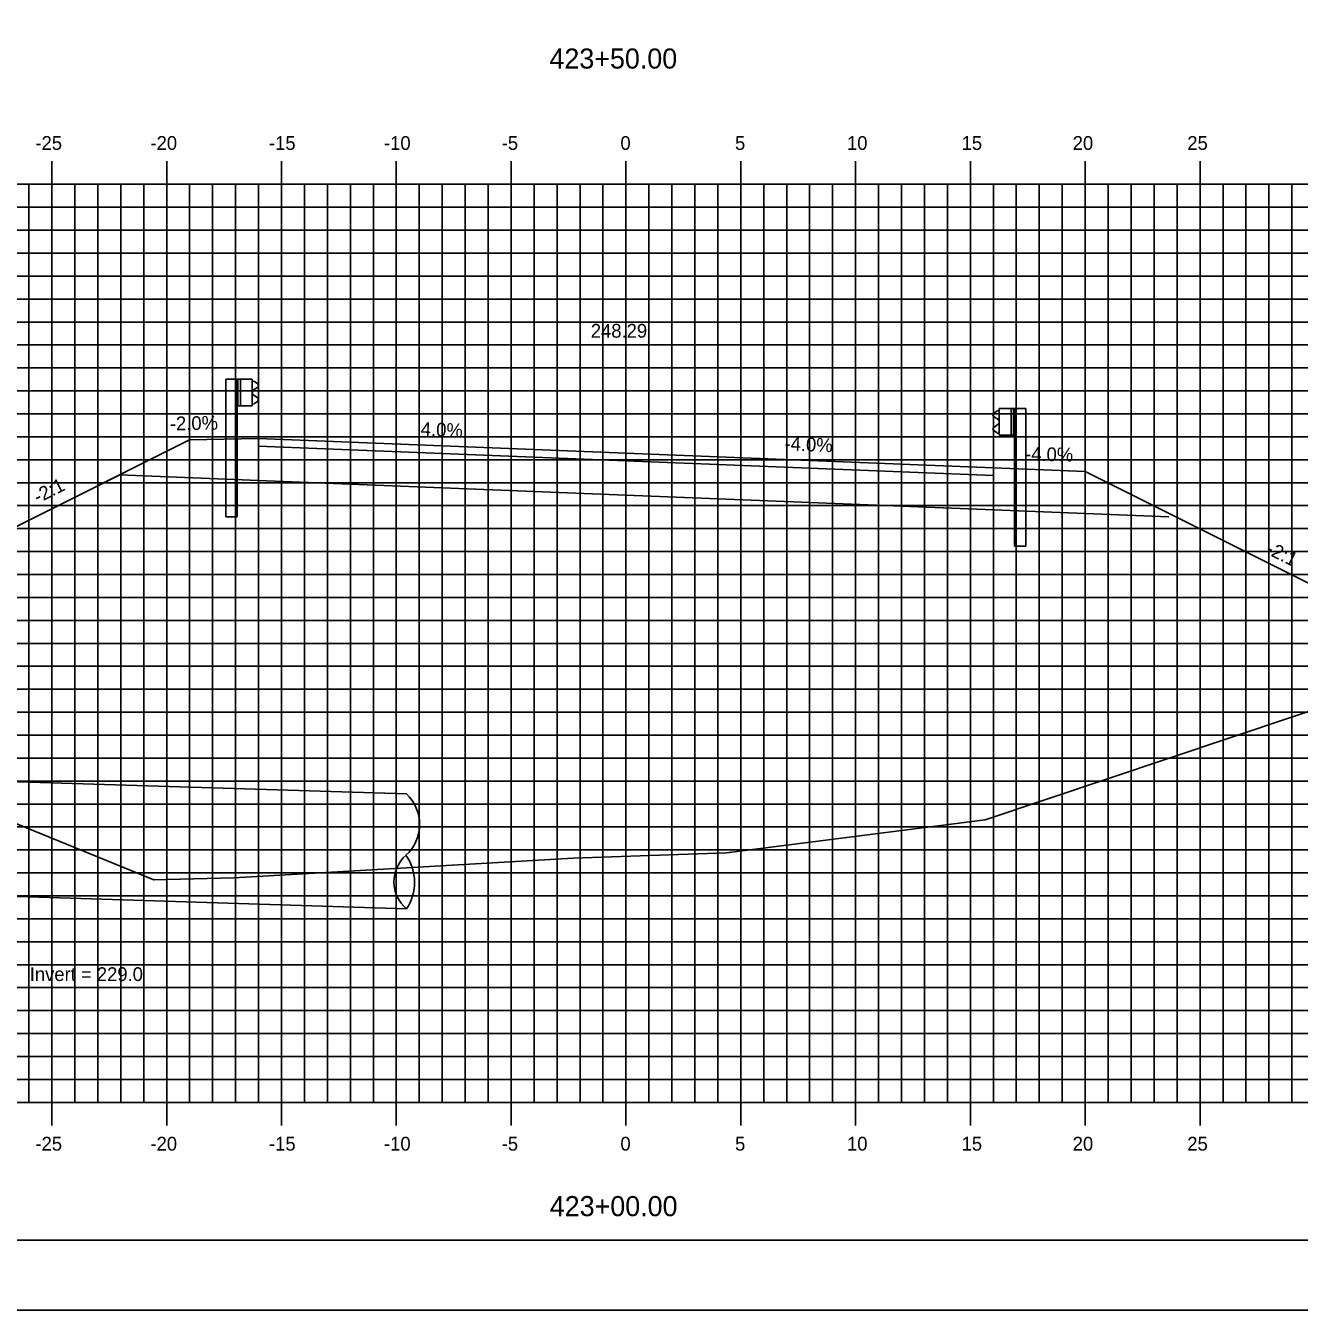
# Model space of a CAD drawing. Extents: x 1160718 to 1173142, y 616002 to 617630.
# Drawn here: x 1170158 to 1170213.5, y 616613.9 to 616669.8 of the extents above; entities that cross this region are included whole.
import ezdxf

# ---------------------------------------------------------------- set-up
doc = ezdxf.new("R2010")
doc.units = 0
for name, color, linetype in [('ANNOTATION', 7, 'Continuous'), ('BORDER', 7, 'Continuous'), ('D_Drainage_Text', 7, 'Continuous'), ('D_Guardrail_Beam_Lt', 7, 'Continuous'), ('D_Guardrail_Beam_Rt', 7, 'Continuous'), ('D_Roadway_Centerline', 7, 'Continuous'), ('D_Roadway_Centerline_Text', 7, 'Continuous'), ('D_Roadway_Edge_Shoulder', 7, 'Continuous'), ('D_Roadway_Edge_TW', 7, 'Continuous'), ('D_Roadway_Pavement', 7, 'Continuous'), ('D_Roadway_SlopeLines', 7, 'Continuous'), ('D_Roadway_SubGrade', 7, 'Continuous'), ('H_V ANNOTATION', 7, 'Continuous'), ('MAJOR', 7, 'Continuous'), ('MINOR', 7, 'Continuous'), ('PLOT BOUNDARY', 7, 'Continuous'), ('S_Roadway_Centerline', 7, 'Continuous'), ('SHADING', 7, 'Continuous')]:
    doc.layers.add(name, color=color, linetype=linetype)

msp = doc.modelspace()

# ---------------------------------------------------------------- linework, layer by layer
at = {"layer": 'ANNOTATION'}
msp.add_line((1170200.151, 616650.575), (1170204.151, 616650.415), dxfattribs=at)
at = {"layer": 'BORDER'}
msp.add_line((1170109.151, 616616.928), (1170269.151, 616616.928), dxfattribs=at)
at = {"layer": 'D_Drainage_Text'}
for p, q in [((1170174.597, 616636.365), (1170155.309, 616636.976)), ((1170174.597, 616631.363), (1170155.309, 616631.974))]:
    msp.add_line(p, q, dxfattribs=at)
for centre, radius, start, end in [((1170173.344, 616635.042), 1.822, 312.4159, 46.5629), ((1170175.585, 616632.54), 1.537, 131.1675, 229.9998), ((1170172.881, 616632.512), 2.065, 326.1716, 34.9956)]:
    msp.add_arc(centre, radius, start, end, dxfattribs=at)
at = {"layer": 'D_Guardrail_Beam_Lt'}
for p, q in [((1170166.723, 616654.439), (1170166.723, 616648.439)), ((1170167.194, 616654.439), (1170166.723, 616654.439)), ((1170167.881, 616654.439), (1170167.194, 616654.439)), ((1170167.194, 616654.439), (1170167.194, 616653.272)), ((1170167.256, 616654.439), (1170167.256, 616653.272)), ((1170167.36, 616654.439), (1170167.36, 616653.272)), ((1170167.881, 616653.272), (1170167.881, 616654.439)), ((1170167.881, 616654.355), (1170167.955, 616654.341)), ((1170168.114, 616654.091), (1170167.919, 616653.955)), ((1170167.971, 616654.334), (1170168.114, 616654.234)), ((1170167.885, 616653.89), (1170167.885, 616653.82)), ((1170167.919, 616653.756), (1170168.114, 616653.62)), ((1170168.114, 616653.476), (1170167.971, 616653.376)), ((1170167.194, 616653.272), (1170167.881, 616653.272)), ((1170167.214, 616648.439), (1170167.214, 616653.272)), ((1170167.955, 616653.37), (1170167.881, 616653.355)), ((1170167.214, 616648.439), (1170166.723, 616648.439))]:
    msp.add_line(p, q, dxfattribs=at)
for centre, major_axis, start_param, end_param in [((1170167.964, 616653.89), (-0.0789, 0), 5.323254, 6.283185), ((1170167.947, 616654.3), (0.0417, 0), 0.959931, 1.376053), ((1170168.064, 616654.162), (0.0877, 0), 5.323254, 7.243116), ((1170167.964, 616653.82), (-0.0789, 0), 6.283185, 7.243116), ((1170167.947, 616653.41), (0.0417, 0), 4.907132, 5.323254), ((1170168.064, 616653.548), (0.0877, 0), 5.323254, 7.243116)]:
    msp.add_ellipse(centre, major_axis=major_axis, ratio=0.995501, start_param=start_param, end_param=end_param, dxfattribs=at)
at = {"layer": 'D_Guardrail_Beam_Rt'}
for p, q in [((1170200.315, 616653.055), (1170200.172, 616652.955)), ((1170200.405, 616653.076), (1170200.331, 616653.061)), ((1170200.405, 616653.159), (1170201.092, 616653.159)), ((1170200.405, 616651.993), (1170200.405, 616653.159)), ((1170200.926, 616653.159), (1170200.926, 616651.993)), ((1170201.03, 616653.159), (1170201.03, 616651.993)), ((1170201.092, 616653.159), (1170201.563, 616653.159)), ((1170201.092, 616653.159), (1170201.092, 616651.993)), ((1170201.563, 616653.159), (1170201.563, 616647.159)), ((1170200.172, 616652.812), (1170200.367, 616652.675)), ((1170200.367, 616652.476), (1170200.172, 616652.34)), ((1170200.401, 616652.611), (1170200.401, 616652.541)), ((1170200.172, 616652.197), (1170200.315, 616652.097)), ((1170200.331, 616652.09), (1170200.405, 616652.076)), ((1170201.092, 616651.993), (1170200.405, 616651.993)), ((1170201.072, 616647.159), (1170201.072, 616651.993)), ((1170201.072, 616647.159), (1170201.563, 616647.159))]:
    msp.add_line(p, q, dxfattribs=at)
for centre, major_axis, start_param, end_param in [((1170200.222, 616652.883), (-0.0877, 0), 5.323254, 7.243116), ((1170200.339, 616653.021), (-0.0417, 0), 4.907132, 5.323254), ((1170200.222, 616652.269), (-0.0877, 0), 5.323254, 7.243116), ((1170200.322, 616652.611), (0.0789, 0), 0, 0.959931), ((1170200.322, 616652.541), (0.0789, 0), 5.323254, 6.283185), ((1170200.339, 616652.131), (-0.0417, 0), 0.959931, 1.376053)]:
    msp.add_ellipse(centre, major_axis=major_axis, ratio=0.995501, start_param=start_param, end_param=end_param, dxfattribs=at)
at = {"layer": 'D_Roadway_Edge_Shoulder'}
for points in [[(1170168.151, 616651.855), (1170168.151, 616651.522)], [(1170200.151, 616650.575), (1170200.151, 616650.242)]]:
    msp.add_lwpolyline(points, dxfattribs=at)
at = {"layer": 'D_Roadway_Edge_TW'}
msp.add_lwpolyline([(1170168.151, 616651.522), (1170168.151, 616651.855), (1170184.151, 616651.215), (1170200.151, 616650.575), (1170200.151, 616650.242), (1170184.151, 616650.882)], close=True, dxfattribs=at)
at = {"layer": 'D_Roadway_Pavement'}
msp.add_lwpolyline([(1170168.151, 616651.522), (1170168.151, 616651.522), (1170184.151, 616650.882), (1170200.151, 616650.242), (1170200.151, 616650.242), (1170184.151, 616650.882)], close=True, dxfattribs=at)
for points in [[(1170168.151, 616651.522), (1170168.151, 616651.522)], [(1170168.151, 616651.522), (1170168.151, 616651.522)], [(1170200.151, 616650.242), (1170200.151, 616650.242)], [(1170200.151, 616650.242), (1170200.151, 616650.242)]]:
    msp.add_lwpolyline(points, dxfattribs=at)
at = {"layer": 'D_Roadway_SlopeLines'}
msp.add_lwpolyline([(1170165.151, 616651.795), (1170154.068, 616646.254)], dxfattribs=at)
at = {"layer": 'D_Roadway_SubGrade'}
for p, q in [((1170165.151, 616651.795), (1170161.163, 616649.801)), ((1170168.151, 616651.855), (1170165.151, 616651.795)), ((1170168.151, 616650.022), (1170168.151, 616651.855)), ((1170168.151, 616650.022), (1170168.151, 616651.522)), ((1170168.151, 616651.522), (1170184.151, 616650.882)), ((1170184.151, 616650.882), (1170200.151, 616650.242)), ((1170200.151, 616648.742), (1170200.151, 616650.575)), ((1170200.151, 616650.242), (1170200.151, 616648.742)), ((1170204.151, 616650.415), (1170220.578, 616642.202))]:
    msp.add_line(p, q, dxfattribs=at)
at = {"layer": 'MAJOR'}
for p, q in [((1170159.151, 616663.93), (1170159.151, 616662.928)), ((1170164.151, 616663.93), (1170164.151, 616662.928)), ((1170169.151, 616663.93), (1170169.151, 616662.928)), ((1170174.151, 616663.93), (1170174.151, 616662.928)), ((1170179.151, 616663.93), (1170179.151, 616662.928)), ((1170184.151, 616663.93), (1170184.151, 616662.928)), ((1170189.151, 616663.93), (1170189.151, 616662.928)), ((1170194.151, 616663.93), (1170194.151, 616662.928)), ((1170199.151, 616663.93), (1170199.151, 616662.928)), ((1170204.151, 616663.93), (1170204.151, 616662.928)), ((1170209.151, 616663.93), (1170209.151, 616662.928)), ((1170114.151, 616662.928), (1170254.151, 616662.928)), ((1170114.151, 616662.928), (1170254.151, 616662.928)), ((1170159.151, 616622.928), (1170159.151, 616662.928)), ((1170164.151, 616622.928), (1170164.151, 616662.928)), ((1170169.151, 616622.928), (1170169.151, 616662.928)), ((1170174.151, 616622.928), (1170174.151, 616662.928)), ((1170179.151, 616622.928), (1170179.151, 616662.928)), ((1170184.151, 616622.928), (1170184.151, 616662.928)), ((1170189.151, 616622.928), (1170189.151, 616662.928)), ((1170194.151, 616622.928), (1170194.151, 616662.928)), ((1170199.151, 616622.928), (1170199.151, 616662.928)), ((1170204.151, 616622.928), (1170204.151, 616662.928)), ((1170209.151, 616622.928), (1170209.151, 616662.928)), ((1170114.151, 616657.928), (1170254.151, 616657.928)), ((1170114.151, 616652.928), (1170254.151, 616652.928)), ((1170114.151, 616647.928), (1170254.151, 616647.928)), ((1170114.151, 616642.928), (1170254.151, 616642.928)), ((1170114.151, 616637.928), (1170254.151, 616637.928)), ((1170114.151, 616632.928), (1170254.151, 616632.928)), ((1170114.151, 616627.928), (1170254.151, 616627.928)), ((1170114.151, 616622.928), (1170254.151, 616622.928)), ((1170114.151, 616622.928), (1170254.151, 616622.928)), ((1170159.151, 616621.926), (1170159.151, 616622.928)), ((1170164.151, 616621.926), (1170164.151, 616622.928)), ((1170169.151, 616621.926), (1170169.151, 616622.928)), ((1170174.151, 616621.926), (1170174.151, 616622.928)), ((1170179.151, 616621.926), (1170179.151, 616622.928)), ((1170184.151, 616621.926), (1170184.151, 616622.928)), ((1170189.151, 616621.926), (1170189.151, 616622.928)), ((1170194.151, 616621.926), (1170194.151, 616622.928)), ((1170199.151, 616621.926), (1170199.151, 616622.928)), ((1170204.151, 616621.926), (1170204.151, 616622.928)), ((1170209.151, 616621.926), (1170209.151, 616622.928))]:
    msp.add_line(p, q, dxfattribs=at)
at = {"layer": 'MINOR'}
for p, q in [((1170158.151, 616622.928), (1170158.151, 616662.928)), ((1170160.151, 616622.928), (1170160.151, 616662.928)), ((1170161.151, 616622.928), (1170161.151, 616662.928)), ((1170162.151, 616622.928), (1170162.151, 616662.928)), ((1170163.151, 616622.928), (1170163.151, 616662.928)), ((1170165.151, 616622.928), (1170165.151, 616662.928)), ((1170166.151, 616622.928), (1170166.151, 616662.928)), ((1170167.151, 616622.928), (1170167.151, 616662.928)), ((1170168.151, 616622.928), (1170168.151, 616662.928)), ((1170170.151, 616622.928), (1170170.151, 616662.928)), ((1170171.151, 616622.928), (1170171.151, 616662.928)), ((1170172.151, 616622.928), (1170172.151, 616662.928)), ((1170173.151, 616622.928), (1170173.151, 616662.928)), ((1170175.151, 616622.928), (1170175.151, 616662.928)), ((1170176.151, 616622.928), (1170176.151, 616662.928)), ((1170177.151, 616622.928), (1170177.151, 616662.928)), ((1170178.151, 616622.928), (1170178.151, 616662.928)), ((1170180.151, 616622.928), (1170180.151, 616662.928)), ((1170181.151, 616622.928), (1170181.151, 616662.928)), ((1170182.151, 616622.928), (1170182.151, 616662.928)), ((1170183.151, 616622.928), (1170183.151, 616662.928)), ((1170185.151, 616622.928), (1170185.151, 616662.928)), ((1170186.151, 616622.928), (1170186.151, 616662.928)), ((1170187.151, 616622.928), (1170187.151, 616662.928)), ((1170188.151, 616622.928), (1170188.151, 616662.928)), ((1170190.151, 616622.928), (1170190.151, 616662.928)), ((1170191.151, 616622.928), (1170191.151, 616662.928)), ((1170192.151, 616622.928), (1170192.151, 616662.928)), ((1170193.151, 616622.928), (1170193.151, 616662.928)), ((1170195.151, 616622.928), (1170195.151, 616662.928)), ((1170196.151, 616622.928), (1170196.151, 616662.928)), ((1170197.151, 616622.928), (1170197.151, 616662.928)), ((1170198.151, 616622.928), (1170198.151, 616662.928)), ((1170200.151, 616622.928), (1170200.151, 616662.928)), ((1170201.151, 616622.928), (1170201.151, 616662.928)), ((1170202.151, 616622.928), (1170202.151, 616662.928)), ((1170203.151, 616622.928), (1170203.151, 616662.928)), ((1170205.151, 616622.928), (1170205.151, 616662.928)), ((1170206.151, 616622.928), (1170206.151, 616662.928)), ((1170207.151, 616622.928), (1170207.151, 616662.928)), ((1170208.151, 616622.928), (1170208.151, 616662.928)), ((1170210.151, 616622.928), (1170210.151, 616662.928)), ((1170211.151, 616622.928), (1170211.151, 616662.928)), ((1170212.151, 616622.928), (1170212.151, 616662.928)), ((1170213.151, 616622.928), (1170213.151, 616662.928)), ((1170114.151, 616661.928), (1170254.151, 616661.928)), ((1170114.151, 616660.928), (1170254.151, 616660.928)), ((1170114.151, 616659.928), (1170254.151, 616659.928)), ((1170114.151, 616658.928), (1170254.151, 616658.928)), ((1170114.151, 616656.928), (1170254.151, 616656.928)), ((1170114.151, 616655.928), (1170254.151, 616655.928)), ((1170114.151, 616654.928), (1170254.151, 616654.928)), ((1170114.151, 616653.928), (1170254.151, 616653.928)), ((1170114.151, 616651.928), (1170254.151, 616651.928)), ((1170114.151, 616650.928), (1170254.151, 616650.928)), ((1170114.151, 616649.928), (1170254.151, 616649.928)), ((1170114.151, 616648.928), (1170254.151, 616648.928)), ((1170114.151, 616646.928), (1170254.151, 616646.928)), ((1170114.151, 616645.928), (1170254.151, 616645.928)), ((1170114.151, 616644.928), (1170254.151, 616644.928)), ((1170114.151, 616643.928), (1170254.151, 616643.928)), ((1170114.151, 616641.928), (1170254.151, 616641.928)), ((1170114.151, 616640.928), (1170254.151, 616640.928)), ((1170114.151, 616639.928), (1170254.151, 616639.928)), ((1170114.151, 616638.928), (1170254.151, 616638.928)), ((1170114.151, 616636.928), (1170254.151, 616636.928)), ((1170114.151, 616635.928), (1170254.151, 616635.928)), ((1170114.151, 616634.928), (1170254.151, 616634.928)), ((1170114.151, 616633.928), (1170254.151, 616633.928)), ((1170114.151, 616631.928), (1170254.151, 616631.928)), ((1170114.151, 616630.928), (1170254.151, 616630.928)), ((1170114.151, 616629.928), (1170254.151, 616629.928)), ((1170114.151, 616628.928), (1170254.151, 616628.928)), ((1170114.151, 616626.928), (1170254.151, 616626.928)), ((1170114.151, 616625.928), (1170254.151, 616625.928)), ((1170114.151, 616624.928), (1170254.151, 616624.928)), ((1170114.151, 616623.928), (1170254.151, 616623.928))]:
    msp.add_line(p, q, dxfattribs=at)
at = {"layer": 'PLOT BOUNDARY'}
msp.add_lwpolyline([(1170101.057, 616613.869), (1170271.057, 616613.869), (1170271.057, 616723.869), (1170101.057, 616723.869)], close=True, dxfattribs=at)
at = {"layer": 'S_Roadway_Centerline'}
msp.add_lwpolyline([(1170114.151, 616654.034), (1170119.443, 616651.554), (1170130.924, 616646.199), (1170135.528, 616644.078), (1170163.591, 616632.625), (1170167.073, 616632.713), (1170181.848, 616633.572), (1170188.523, 616633.797), (1170199.794, 616635.233), (1170245.321, 616650.498), (1170254.151, 616652.947)], dxfattribs=at)
at = {"layer": 'SHADING'}
msp.add_lwpolyline([(1170162.089, 616650.264), (1170168.151, 616650.022), (1170207.785, 616648.437)], dxfattribs=at)

# ---------------------------------------------------------------- texts
at = {"layer": 'ANNOTATION'}
for s, rotation, p in [('-2.0%', 1.1458, (1170164.295, 616652.202)), ('4.0%', 357.7094, (1170175.207, 616651.974)), ('-4.0%', 357.7094, (1170191.046, 616651.34)), ('-4.0%', 358.8542, (1170201.526, 616650.888)), ('-2:1', 26.5651, (1170158.538, 616649.007)), ('-2:1', 333.4349, (1170211.967, 616646.872))]:
    msp.add_text(s, height=0.6, rotation=rotation, dxfattribs=at).set_placement(p)
at = {"layer": 'D_Roadway_Centerline'}
for s, p in [('C', (1170184.145, 616651.215)), ('L', (1170184.151, 616651.208))]:
    msp.add_text(s, height=0.0146, dxfattribs=at).set_placement(p)
at = {"layer": 'D_Roadway_Centerline_Text'}
for s, p in [('248.29', (1170182.62, 616656.247)), ('Invert = 229.0', (1170158.189, 616628.216))]:
    msp.add_text(s, height=0.6, dxfattribs=at).set_placement(p)
at = {"layer": 'H_V ANNOTATION'}
for s, height, p in [('423+50.00', 0.875, (1170180.819, 616667.971)), ('-25', 0.6, (1170158.436, 616664.428)), ('-20', 0.6, (1170163.444, 616664.428)), ('-15', 0.6, (1170168.607, 616664.428)), ('-10', 0.6, (1170173.615, 616664.428)), ('-5', 0.6, (1170178.741, 616664.428)), ('0', 0.6, (1170183.91, 616664.428)), ('5', 0.6, (1170188.902, 616664.428)), ('10', 0.6, (1170193.776, 616664.428)), ('15', 0.6, (1170198.768, 616664.428)), ('20', 0.6, (1170203.605, 616664.428)), ('25', 0.6, (1170208.597, 616664.428)), ('-25', 0.6, (1170158.436, 616620.828)), ('-20', 0.6, (1170163.444, 616620.828)), ('-15', 0.6, (1170168.607, 616620.828)), ('-10', 0.6, (1170173.615, 616620.828)), ('-5', 0.6, (1170178.741, 616620.828)), ('0', 0.6, (1170183.91, 616620.828)), ('5', 0.6, (1170188.902, 616620.828)), ('10', 0.6, (1170193.776, 616620.828)), ('15', 0.6, (1170198.768, 616620.828)), ('20', 0.6, (1170203.605, 616620.828)), ('25', 0.6, (1170208.597, 616620.828)), ('423+00.00', 0.875, (1170180.834, 616617.971))]:
    msp.add_text(s, height=height, dxfattribs=at).set_placement(p)

doc.saveas('drawing.dxf')
